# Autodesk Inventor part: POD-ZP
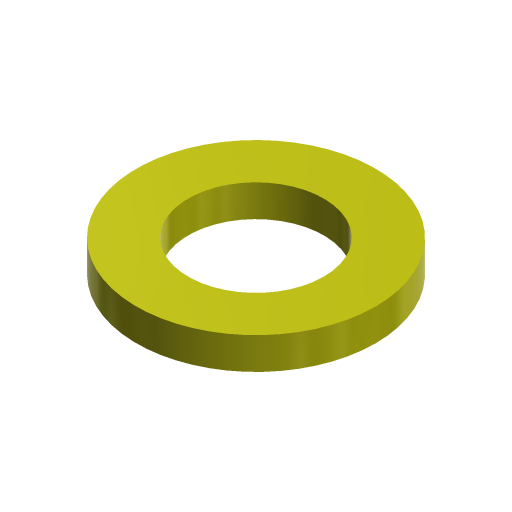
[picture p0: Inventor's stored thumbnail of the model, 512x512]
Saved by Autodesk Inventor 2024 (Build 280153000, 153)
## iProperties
Company: ATC
Shininess: 20.0
Length Units: 11269
Angle Units: 11279
Time Units: 11290
Mass Units: 11283
Length Display Precision: 3
Angle Display Precision: 2
Compacted: True
Created: 2023-03
Part Number: POD-ZP
Document SubType Name: Modeling
Designer: Andrzej Jaskulski
Material: Kurs-AJ
Density: 1 g/cm^3
Appearance: Żółta
Checked By: A.J.
Engr Approved By: Andrzej Jaskulski
Mfg Approved By: Andrzej Jaskulski
Authority: A.J.
Density: 0.0
Volumn: 0.0
Area: 0.0
PropertySet Name: Model Information
Control State: 0
Master: False
Checked Out: False
Title: A.J.: Kurs R2024-MEP
Author: Andrzej Jaskulski
Revision Number: 1/24
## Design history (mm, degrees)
sketch "Sketch1"
  geometry: C1 r 4.25 at (0, 0); C2 r 7.5 at (0, 0)
  constraints: 2 centre point, 1 coincident
  dimensions: "d2" = 8.5 diameter of C1; "d3" = 15 diameter of C2
extrude "Extrusion1" new body sketch "Sketch1" distance "d0" = 2; taper "d1" = 0 deg
node "Bryła1"
node "Korpusy bryłowe"
node "Korpusy powierzchniowe"
